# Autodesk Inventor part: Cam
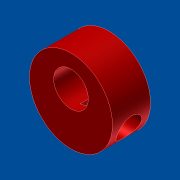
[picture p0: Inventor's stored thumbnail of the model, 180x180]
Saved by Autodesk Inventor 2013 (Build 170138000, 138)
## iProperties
Shininess: 20.0
Length Units: 11269
Angle Units: 11279
Time Units: 11290
Mass Units: 11283
Length Display Precision: 3
Angle Display Precision: 2
Created: 2001-04
Part Number: Cam
Material: Standard
Document SubType Name: Modellieren
Designer: dl
Density: 1 g/cm^3
Density: 0.0
Volumn: 0.0
Area: 0.0
PropertySet Name: Model Information
Control State: 0
Master: False
Checked Out: False
Author: dl
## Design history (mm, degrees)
sketch "Sketch1"
  geometry: C1 r 6 at (0, 0)
  constraints: 1 centre point
  dimensions: "d0" = 12 diameter of C1
extrude "Extrusion1" new body sketch "Sketch1" distance "d1" = 5.5; taper "d2" = 0 deg
sketch "Sketch3"
  geometry: L1 (0, -0.55)-(0, 7.15) reference; L2 (-6, 0)-(6, 0) reference; C1 r 1.75 at (-2, 2.75)
  constraints: 1 centre point
  dimensions: "d12" = 2 distance from line of C1.centre L1; "d13" = 2.75 distance from line of C1.centre L2; "d16" = 3.5 diameter of C1
extrude "Extrusion2" cut sketch "Sketch3" distance "d14" = 10; taper "d15" = 0 deg
body "Solid1"
sketch "Sketch2"
  geometry: C1 r 6 at (0, 0) reference; 1 further point
  dimensions: "d3" = 1.5 distance of C1.centre point (0, 1.5); "d4" = 0 horizontal distance of C1.centre point (0, 1.5)
hole "Hole1" sketch "Sketch2" diameter "d5" = 5; stored, may be unused: countersink angle "d9" = 60 deg, drill point angle "d11" = 118 deg; dims "d6" = 6, "d7" = 4, "d8" = 2, "d10" = 8
